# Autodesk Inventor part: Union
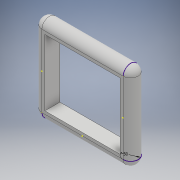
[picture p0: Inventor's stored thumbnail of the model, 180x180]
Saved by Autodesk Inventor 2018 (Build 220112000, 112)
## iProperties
Created: 2022-01
Part Number: Union
Material: Generic
Document SubType Name: Modeling
Designer: Asus
Density: 1 g/cm^3
Appearance: Default
Author: Asus
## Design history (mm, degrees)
sketch "Boceto1"
  geometry: L1 (135, 120)-(-135, 120); L2 (-135, 120)-(-135, -120); L3 (-135, -120)-(135, -120); L4 (135, -120)-(135, 120); L5 (135, 120)-(-135, -120); L6 (-135, 120)-(135, -120); L7 (125, 110)-(-125, 110); L8 (-125, 110)-(-125, -110); L9 (-125, -110)-(125, -110); L10 (125, -110)-(125, 110); L11 (125, 110)-(-125, -110); L12 (-125, 110)-(125, -110); 1 further point
  constraints: 24 end point, 4 midpoint, 4 parallel, 2 horizontal, 2 perpendicular
  dimensions: "d0" = 270 distance of L3.end L2.end; "d1" = 240 distance of L2.end L1.end; "d2" = 250 distance of L9.end L8.end; "d3" = 220 distance of L8.end L7.end
extrude "Extrusión1" new body sketch "Boceto1" distance "d4" = 50; taper "d5" = 0 deg
sketch "Boceto2"
  geometry: L1 (0, 0)-(0, 50) reference; L2 (0, 50)-(0, 0); A1 r 25 centre (0, 25) between (0, 50) and (0, 0); 1 further point
  constraints: 2 end point, 2 point on circle, 1 centre point, 1 collinear, 1 midpoint
extrude "Extrusión2" join sketch "Boceto2" distance "d6" = 270; taper "d7" = 0 deg
revolve "Revolución1" stored, may be unused: angle "d8" = 90 deg
sketch "Boceto4"
  geometry: L1 (0, 50)-(0, 0); A1 r 25 centre (0, 25) between (0, 50) and (0, 0); 1 further point
  constraints: 2 end point, 2 point on circle, 1 centre point
  dimensions: "d9" = 50 diameter of A1
extrude "Extrusión3" join sketch "Boceto4" distance "d10" = 240; taper "d11" = 0 deg
revolve "Revolución2" stored, may be unused: angle "d12" = 90 deg
sketch "Boceto5"
  geometry: L1 (0, 0)-(0, 50) reference; L2 (0, 50)-(0, 0); A1 r 25 centre (0, 25) between (0, 50) and (0, 0); A2 r 25 centre (0, 25) between (0, 50) and (0, 0) reference; 1 further point
  constraints: 2 end point, 2 point on circle, 1 centre point, 1 midpoint, 1 vertical
extrude "Extrusión4" join sketch "Boceto5" distance "d13" = 270; taper "d14" = 0 deg
revolve "Revolución3" stored, may be unused: angle "d15" = 90 deg
sketch "Boceto6"
  geometry: L1 (0, 50)-(0, 0) reference; L2 (0, 50)-(0, 0); A1 r 25 centre (0, 25) between (0, 50) and (0, 0); 1 further point
  constraints: 2 end point, 2 point on circle, 1 centre point, 1 midpoint, 1 vertical
extrude "Extrusión5" join sketch "Boceto6" distance "d16" = 240; taper "d17" = 0 deg
sketch "Boceto7"
  geometry: L1 (0, 50)-(0, 0) reference; L2 (0, 50)-(0, 0); A1 r 25 centre (0, 25) between (0, 50) and (0, 0); 1 further point
  constraints: 2 end point, 2 point on circle, 1 centre point, 1 midpoint, 1 vertical
revolve "Revolución4" sketch "Boceto7" stored, may be unused: angle "d18" = 90 deg
node "Sólido1"
